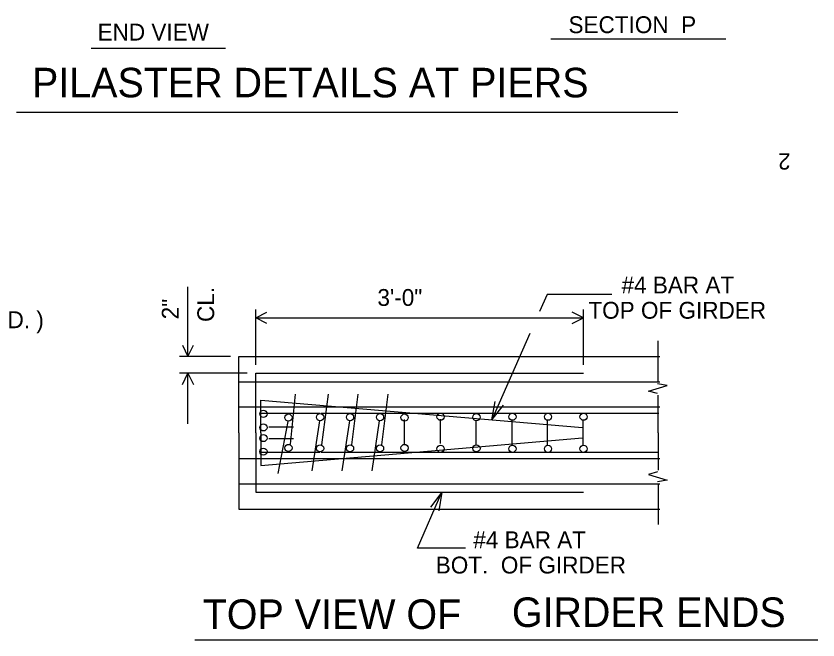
# Model space of a CAD drawing. Extents: x 1005.3 to 1101.9, y 2006.8 to 2073.3.
# Drawn here: x 1062.87 to 1078.74, y 2040.95 to 2053.29 of the extents above; entities that cross this region are included whole.
import ezdxf

# ---------------------------------------------------------------- set-up
doc = ezdxf.new("R2010")
doc.units = 0
for name, color, linetype in [('Level 2', 7, 'Continuous'), ('Level 6', 7, 'Continuous'), ('Level 60', 7, 'Continuous'), ('Level 7', 7, 'Continuous')]:
    doc.layers.add(name, color=color, linetype=linetype)

msp = doc.modelspace()

# ---------------------------------------------------------------- linework, layer by layer
at = {"layer": 'Level 2'}
for p, q in [((1066.274, 2046.558), (1066.274, 2047.936)), ((1073.377, 2047.782), (1073.229, 2047.446)), ((1074.661, 2047.782), (1073.377, 2047.782)), ((1067.614, 2046.392), (1067.614, 2047.485)), ((1074.099, 2046.392), (1074.099, 2047.485)), ((1067.614, 2047.319), (1074.099, 2047.319)), ((1073.039, 2047.012), (1072.287, 2045.302)), ((1075.578, 2046.067), (1075.578, 2046.863)), ((1067.114, 2046.558), (1066.107, 2046.558)), ((1067.281, 2046.558), (1075.611, 2046.558)), ((1067.281, 2045.048), (1067.281, 2046.558)), ((1067.448, 2046.225), (1066.107, 2046.225)), ((1066.274, 2045.225), (1066.274, 2046.225)), ((1067.614, 2046.225), (1074.099, 2046.225)), ((1067.614, 2045.048), (1067.614, 2046.225)), ((1067.281, 2046.058), (1075.611, 2046.058)), ((1075.757, 2045.985), (1075.562, 2046.018)), ((1075.383, 2045.872), (1075.757, 2045.985)), ((1075.562, 2045.823), (1075.383, 2045.872)), ((1067.712, 2045.693), (1074.081, 2045.149)), ((1067.712, 2045.048), (1067.712, 2045.693)), ((1068.301, 2044.822), (1068.398, 2045.808)), ((1068.923, 2044.811), (1069.051, 2045.808)), ((1069.516, 2044.811), (1069.644, 2045.808)), ((1070.108, 2044.811), (1070.237, 2045.808)), ((1075.578, 2045.048), (1075.578, 2045.79)), ((1067.281, 2045.558), (1075.611, 2045.558)), ((1072.287, 2045.302), (1072.349, 2045.668)), ((1072.287, 2045.302), (1072.514, 2045.595)), ((1067.72, 2045.433), (1068.89, 2045.433)), ((1068.906, 2045.433), (1075.587, 2045.433)), ((1068.055, 2044.243), (1068.258, 2045.272)), ((1068.73, 2044.297), (1068.88, 2045.283)), ((1069.323, 2044.297), (1069.473, 2045.283)), ((1069.916, 2044.297), (1070.066, 2045.283)), ((1070.558, 2044.824), (1070.558, 2045.308)), ((1071.269, 2044.836), (1071.269, 2045.32)), ((1071.975, 2044.812), (1071.975, 2045.296)), ((1072.686, 2044.8), (1072.686, 2045.284)), ((1073.389, 2044.8), (1073.389, 2045.284)), ((1074.093, 2044.8), (1074.093, 2045.284)), ((1067.281, 2045.048), (1067.281, 2043.539)), ((1067.614, 2045.048), (1067.614, 2043.872)), ((1067.712, 2045.048), (1067.712, 2044.404)), ((1067.874, 2045.164), (1068.362, 2045.164)), ((1075.578, 2045.048), (1075.578, 2044.307)), ((1067.712, 2044.404), (1074.08, 2044.948)), ((1067.874, 2044.932), (1068.362, 2044.932)), ((1067.72, 2044.664), (1068.89, 2044.664)), ((1068.906, 2044.664), (1075.587, 2044.664)), ((1067.281, 2044.539), (1075.611, 2044.539)), ((1075.562, 2044.274), (1075.383, 2044.225)), ((1075.383, 2044.225), (1075.757, 2044.112)), ((1075.757, 2044.112), (1075.562, 2044.079)), ((1067.281, 2044.039), (1075.611, 2044.039)), ((1075.578, 2044.03), (1075.578, 2043.234)), ((1067.614, 2043.872), (1074.099, 2043.872)), ((1070.812, 2042.767), (1071.298, 2043.872)), ((1071.298, 2043.872), (1071.071, 2043.579)), ((1071.298, 2043.872), (1071.236, 2043.506)), ((1067.281, 2043.539), (1075.611, 2043.539)), ((1071.765, 2042.767), (1070.812, 2042.767)), ((1066.41, 2040.952), (1078.738, 2040.952))]:
    msp.add_line(p, q, dxfattribs=at)
for points in [[(1067.837, 2047.207), (1067.614, 2047.319), (1067.837, 2047.43)], [(1073.877, 2047.207), (1074.099, 2047.319), (1073.877, 2047.43)], [(1066.163, 2046.781), (1066.274, 2046.558), (1066.385, 2046.781)], [(1066.163, 2046.003), (1066.274, 2046.225), (1066.385, 2046.003)]]:
    msp.add_lwpolyline(points, dxfattribs=at)
for centre in [(1067.767, 2045.422), (1068.262, 2045.349), (1068.888, 2045.357), (1069.481, 2045.357), (1070.074, 2045.357), (1070.559, 2045.349), (1071.271, 2045.365), (1071.981, 2045.357), (1072.693, 2045.365), (1073.396, 2045.365), (1074.1, 2045.365), (1067.767, 2045.154), (1067.767, 2044.943), (1067.767, 2044.675), (1068.262, 2044.748), (1068.888, 2044.74), (1069.481, 2044.74), (1070.074, 2044.74), (1070.559, 2044.748), (1071.271, 2044.732), (1071.981, 2044.74), (1072.693, 2044.732), (1073.396, 2044.732), (1074.1, 2044.732)]:
    msp.add_circle(centre, 0.0708, dxfattribs=at)
at = {"layer": 'Level 7'}
for p, q in [((1073.451, 2052.838), (1076.917, 2052.838)), ((1064.359, 2052.654), (1067.014, 2052.654)), ((1062.884, 2051.386), (1075.968, 2051.386))]:
    msp.add_line(p, q, dxfattribs=at)

# ---------------------------------------------------------------- texts
at = {"layer": 'Level 2'}
for s, height, p in [('#4 BAR AT', 0.3333, (1074.851, 2047.803)), ('3\'-0"', 0.3333, (1070.022, 2047.556)), ('   TOP OF GIRDER', 0.33333, (1073.824, 2047.303)), ('#4 BAR AT', 0.3333, (1071.919, 2042.766)), ('   BOT.  OF GIRDER', 0.33333, (1070.804, 2042.266)), ('TOP VIEW OF', 0.58333, (1066.565, 2041.17)), (' GIRDER ENDS', 0.58333, (1072.465, 2041.209))]:
    msp.add_text(s, height=height, dxfattribs=at).set_placement(p)
for s, p in [('CL.', (1066.792, 2047.238)), ('2"', (1066.09, 2047.291))]:
    msp.add_text(s, height=0.3333, rotation=90, dxfattribs=at).set_placement(p)
at = {"layer": 'Level 6'}
msp.add_text('ANCHOR PLATE IS USED. )', height=0.33333, dxfattribs=at).set_placement((1057.651, 2047.116))
at = {"layer": 'Level 60'}
msp.add_text('2', height=0.323, rotation=180, dxfattribs=at).set_placement((1078.194, 2050.574))
at = {"layer": 'Level 7'}
for s, height, p in [('SECTION  P', 0.3333, (1073.802, 2052.949)), ('END VIEW', 0.3333, (1064.485, 2052.803)), ('PILASTER DETAILS AT PIERS', 0.58333, (1063.188, 2051.68))]:
    msp.add_text(s, height=height, dxfattribs=at).set_placement(p)

doc.saveas('drawing.dxf')
